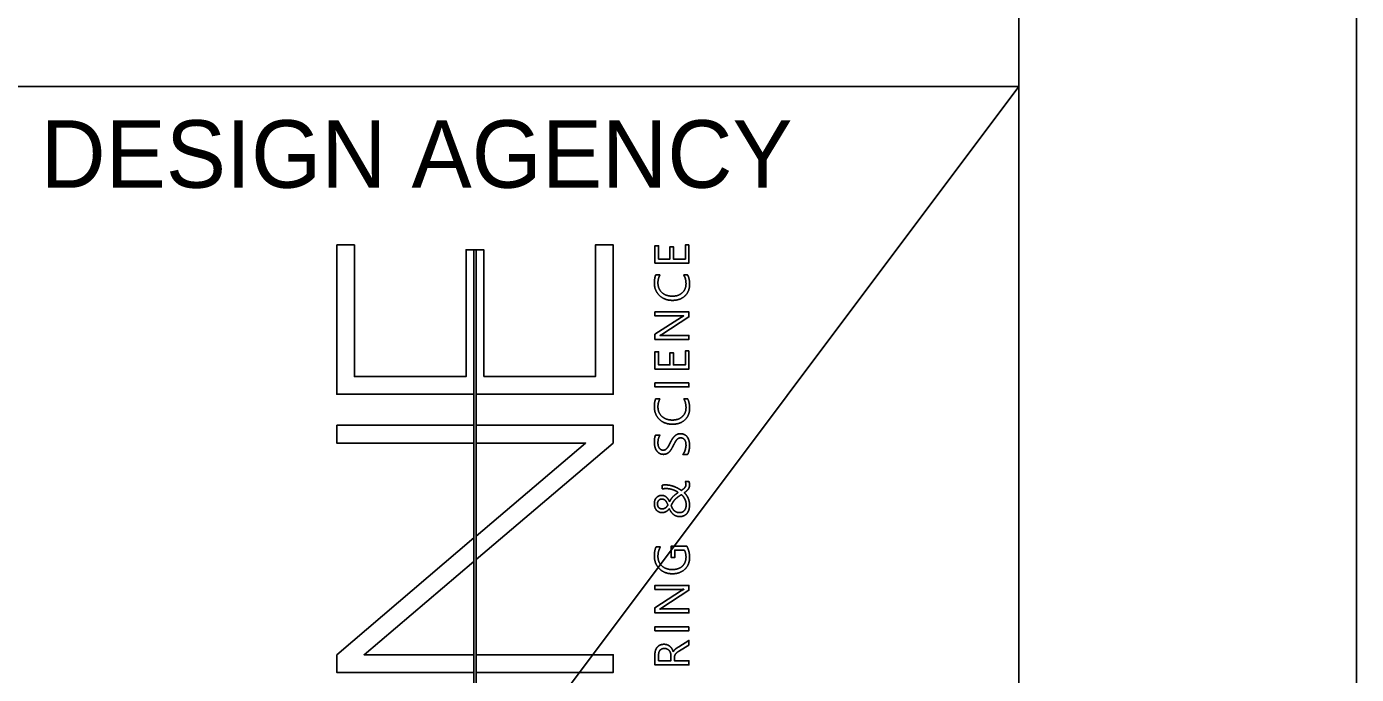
# Model space of a CAD drawing. Extents: x -2 to 1376856, y -4 to 32.
# Drawn here: x 32.029 to 34, y 4.129 to 5.089 of the extents above; entities that cross this region are included whole.
import ezdxf

# ---------------------------------------------------------------- set-up
doc = ezdxf.new("R2010")
doc.units = 0
for name, color, linetype in [('SC_Scratch1', 7, 'Continuous'), ('SH_Border', 7, 'Continuous'), ('SH_Cut_Line', 7, 'Continuous'), ('SH_Data', 7, 'Continuous')]:
    doc.layers.add(name, color=color, linetype=linetype)

msp = doc.modelspace()

# ---------------------------------------------------------------- linework, layer by layer
at = {"layer": 'SC_Scratch1'}
msp.add_line((32, 3), (33.5, 5), dxfattribs=at)
at = {"layer": 'SH_Border'}
msp.add_line((32, 5), (33.5, 5), dxfattribs=at)
msp.add_lwpolyline([(1.5, 21.5), (33.5, 21.5), (33.5, 0.5), (1.5, 0.5)], close=True, dxfattribs=at)
at = {"layer": 'SH_Cut_Line'}
msp.add_lwpolyline([(0, 0), (34, 0), (34, 22), (0, 22)], close=True, dxfattribs=at)
at = {"layer": 'SH_Data'}
for p, q in [((32.489, 4.7652), (32.5153, 4.7652)), ((32.489, 4.5439), (32.489, 4.7652)), ((32.5153, 4.5702), (32.5153, 4.7652)), ((32.6807, 4.5702), (32.6807, 4.7581)), ((32.6807, 4.7581), (32.6923, 4.7581)), ((32.6923, 4.7581), (32.6923, 3.9731)), ((32.6923, 4.7581), (32.6923, 4.5439)), ((32.6923, 4.7581), (32.6954, 4.7581)), ((32.6954, 4.7581), (32.6954, 3.9731)), ((32.6954, 4.7581), (32.6954, 4.5439)), ((32.6954, 4.7581), (32.707, 4.7581)), ((32.707, 4.5702), (32.707, 4.7581)), ((32.8724, 4.7652), (32.8988, 4.7652)), ((32.8724, 4.5702), (32.8724, 4.7652)), ((32.8988, 4.5439), (32.8988, 4.7652)), ((32.9617, 4.7208), (32.968, 4.7208)), ((33.0032, 4.7208), (33.0089, 4.7208)), ((33.0035, 4.6602), (33.0035, 4.6603)), ((32.9676, 4.631), (32.9676, 4.6308)), ((32.5153, 4.5702), (32.6807, 4.5702)), ((32.707, 4.5702), (32.8724, 4.5702)), ((32.489, 4.5439), (32.6923, 4.5439)), ((32.6954, 4.5439), (32.8988, 4.5439)), ((32.9617, 4.5373), (32.968, 4.5373)), ((33.0032, 4.5373), (33.0089, 4.5373)), ((32.489, 4.4717), (32.489, 4.4981)), ((32.489, 4.4981), (32.6923, 4.4981)), ((32.6923, 4.4981), (32.6923, 4.4717)), ((32.6954, 4.4981), (32.6954, 4.4717)), ((32.6954, 4.4981), (32.8988, 4.4981)), ((32.8988, 4.4717), (32.8988, 4.4981)), ((32.9615, 4.4834), (32.9681, 4.4834)), ((32.489, 4.4717), (32.6923, 4.4717)), ((32.6954, 4.3337), (32.8577, 4.4717)), ((32.8988, 4.4717), (32.6954, 4.2989)), ((32.6954, 4.4717), (32.8577, 4.4717)), ((33.009, 4.4549), (33.002, 4.4549)), ((33.0109, 4.4148), (33.0055, 4.4148)), ((32.9715, 4.4092), (32.9715, 4.4036)), ((33.0118, 4.4094), (33.0118, 4.4094)), ((32.9709, 4.3886), (32.9709, 4.3886)), ((33.0068, 4.3798), (33.0068, 4.3798)), ((32.489, 4.158), (32.6923, 4.331)), ((32.6923, 4.331), (32.6923, 4.2962)), ((32.6954, 4.3337), (32.6954, 4.2989)), ((32.9623, 4.318), (32.9689, 4.318)), ((32.6923, 4.2962), (32.5296, 4.158)), ((33.0035, 4.255), (33.0035, 4.2551)), ((32.9676, 4.2258), (32.9676, 4.2256)), ((32.489, 4.1316), (32.489, 4.158)), ((32.5296, 4.158), (32.6923, 4.158)), ((32.6923, 4.158), (32.6923, 4.1316)), ((32.6954, 4.158), (32.6954, 4.1316)), ((32.6954, 4.158), (32.8988, 4.158)), ((32.8988, 4.1316), (32.8988, 4.158)), ((32.9877, 4.1622), (32.9876, 4.1622)), ((32.489, 4.1316), (32.6923, 4.1316)), ((32.6954, 4.1316), (32.8988, 4.1316))]:
    msp.add_line(p, q, dxfattribs=at)
for points in [[(32.489, 4.7652), (32.489, 4.5439), (32.6923, 4.5439), (32.6923, 4.7581), (32.6807, 4.7581), (32.6807, 4.5702), (32.5153, 4.5702), (32.5153, 4.7652)], [(32.707, 4.5702), (32.707, 4.7581), (32.6954, 4.7581), (32.6954, 4.5439), (32.8988, 4.5439), (32.8988, 4.7652), (32.8724, 4.7652), (32.8724, 4.5702)], [(33.011, 4.7652), (33.011, 4.7384), (32.9605, 4.7384), (32.9605, 4.7641), (32.9659, 4.7641), (32.9659, 4.7443), (32.9827, 4.7443), (32.9827, 4.7626), (32.988, 4.7626), (32.988, 4.7443), (33.0057, 4.7443), (33.0057, 4.7652)], [(33.011, 4.6081), (33.011, 4.5813), (32.9605, 4.5813), (32.9605, 4.607), (32.9659, 4.607), (32.9659, 4.5873), (32.9827, 4.5873), (32.9827, 4.6055), (32.988, 4.6055), (32.988, 4.5873), (33.0057, 4.5873), (33.0057, 4.6081)], [(33.011, 4.5607), (33.011, 4.5548), (32.9605, 4.5548), (32.9605, 4.5607)], [(32.489, 4.4981), (32.489, 4.4717), (32.6923, 4.4717), (32.6923, 4.4981)], [(32.6954, 4.4981), (32.6954, 4.4717), (32.8577, 4.4717), (32.6954, 4.3337), (32.6954, 4.2989), (32.8988, 4.4717), (32.8988, 4.4981)], [(32.489, 4.158), (32.489, 4.1316), (32.6923, 4.1316), (32.6923, 4.158), (32.5296, 4.158), (32.6923, 4.2962), (32.6923, 4.331)], [(33.011, 4.1993), (33.011, 4.1934), (32.9605, 4.1934), (32.9605, 4.1993)], [(32.6954, 4.158), (32.6954, 4.1316), (32.8988, 4.1316), (32.8988, 4.158)]]:
    msp.add_lwpolyline(points, close=True, dxfattribs=at)
for points in [[(32.8317, 3.9686), (32.6986, 3.9356), (32.6986, 3.9731), (32.6954, 3.9731), (32.6954, 4.7581), (32.6923, 4.7581), (32.6923, 3.9731), (32.6891, 3.9731), (32.6891, 3.9333), (32.6149, 3.9149)], [(32.9961, 4.66), (32.9605, 4.66), (32.9605, 4.6659), (33.011, 4.6659), (33.011, 4.6586), (32.9708, 4.6326)], [(32.9745, 4.6311), (33.011, 4.6311), (33.011, 4.6252), (32.9605, 4.6252), (32.9605, 4.6328), (33.0001, 4.6581)], [(33.0042, 4.3131), (32.99, 4.3131), (32.99, 4.302), (32.9847, 4.302), (32.9847, 4.319), (33.0076, 4.319)], [(32.9961, 4.2547), (32.9605, 4.2547), (32.9605, 4.2607), (33.011, 4.2607), (33.011, 4.2534), (32.9708, 4.2274)], [(32.9745, 4.2258), (33.011, 4.2258), (33.011, 4.2199), (32.9605, 4.2199), (32.9605, 4.2276), (33.0001, 4.2529)], [(32.9969, 4.1637), (33.011, 4.1721), (33.011, 4.1792), (32.9958, 4.1697)], [(32.9605, 4.158), (32.9605, 4.1429), (33.011, 4.1429), (33.011, 4.1489), (32.9895, 4.1489), (32.9895, 4.1537)], [(32.9842, 4.1569), (32.9842, 4.1489), (32.9659, 4.1489), (32.9659, 4.157)]]:
    msp.add_lwpolyline(points, dxfattribs=at)
for points in [[(32.9597, 4.7089), (32.9597, 4.7161), (32.9617, 4.7208)], [(32.968, 4.7208), (32.965, 4.7154), (32.965, 4.7089)], [(33.0066, 4.7077), (33.0066, 4.7153), (33.0032, 4.7208)], [(33.0089, 4.7208), (33.0119, 4.7152), (33.0119, 4.7069)], [(32.9671, 4.6904), (32.9597, 4.6977), (32.9597, 4.7089)], [(32.965, 4.7089), (32.965, 4.7002), (32.9708, 4.6947)], [(32.9867, 4.6831), (32.9746, 4.6831), (32.9671, 4.6904)], [(32.9708, 4.6947), (32.9766, 4.6893), (32.9864, 4.6893)], [(32.9864, 4.6893), (32.9956, 4.6893), (33.0011, 4.6944)], [(33.0011, 4.6944), (33.0066, 4.6994), (33.0066, 4.7077)], [(33.0119, 4.7069), (33.0119, 4.6961), (33.0049, 4.6896)], [(33.0049, 4.6896), (32.998, 4.6831), (32.9867, 4.6831)], [(33.0035, 4.6603), (33.0013, 4.66), (32.9961, 4.66)], [(33.0001, 4.6581), (33.0026, 4.6597), (33.0035, 4.6602)], [(32.9708, 4.6326), (32.9692, 4.6316), (32.9676, 4.631)], [(32.9676, 4.6308), (32.9692, 4.6311), (32.9745, 4.6311)], [(32.9597, 4.5253), (32.9597, 4.5325), (32.9617, 4.5373)], [(32.968, 4.5373), (32.965, 4.5318), (32.965, 4.5253)], [(33.0066, 4.5241), (33.0066, 4.5317), (33.0032, 4.5373)], [(33.0089, 4.5373), (33.0119, 4.5316), (33.0119, 4.5233)], [(32.9671, 4.5068), (32.9597, 4.5141), (32.9597, 4.5253)], [(32.965, 4.5253), (32.965, 4.5166), (32.9708, 4.5112)], [(33.0011, 4.5108), (33.0066, 4.5159), (33.0066, 4.5241)], [(33.0119, 4.5233), (33.0119, 4.5125), (33.0049, 4.506)], [(32.9867, 4.4995), (32.9746, 4.4995), (32.9671, 4.5068)], [(32.9708, 4.5112), (32.9766, 4.5057), (32.9864, 4.5057)], [(32.9864, 4.5057), (32.9956, 4.5057), (33.0011, 4.5108)], [(33.0049, 4.506), (32.998, 4.4995), (32.9867, 4.4995)], [(32.9597, 4.4725), (32.9597, 4.4799), (32.9615, 4.4834)], [(32.9681, 4.4834), (32.965, 4.4789), (32.965, 4.4719)], [(32.9832, 4.4721), (32.9845, 4.4748), (32.986, 4.4772)], [(32.986, 4.4772), (32.9875, 4.4797), (32.9893, 4.4815)], [(32.9893, 4.4815), (32.9911, 4.4833), (32.9933, 4.4844)], [(32.9924, 4.4759), (32.9911, 4.4743), (32.99, 4.4721)], [(32.9951, 4.4784), (32.9936, 4.4775), (32.9924, 4.4759)], [(32.9933, 4.4844), (32.9955, 4.4855), (32.9983, 4.4855)], [(32.9987, 4.4793), (32.9967, 4.4793), (32.9951, 4.4784)], [(32.9983, 4.4855), (33.002, 4.4855), (33.0046, 4.484)], [(33.0045, 4.4766), (33.0025, 4.4793), (32.9987, 4.4793)], [(33.0066, 4.4684), (33.0066, 4.4739), (33.0045, 4.4766)], [(33.0046, 4.484), (33.0072, 4.4826), (33.0088, 4.4801)], [(33.0088, 4.4801), (33.0104, 4.4776), (33.0112, 4.4743)], [(33.0112, 4.4743), (33.0119, 4.4711), (33.0119, 4.4675)], [(32.9605, 4.466), (32.9597, 4.4692), (32.9597, 4.4725)], [(32.9629, 4.4604), (32.9613, 4.4629), (32.9605, 4.466)], [(32.9671, 4.4564), (32.9646, 4.458), (32.9629, 4.4604)], [(32.965, 4.4719), (32.965, 4.4699), (32.9654, 4.468)], [(32.9654, 4.468), (32.9658, 4.4661), (32.9667, 4.4645)], [(32.9667, 4.4645), (32.9677, 4.463), (32.9691, 4.4621)], [(32.9732, 4.4549), (32.9697, 4.4549), (32.9671, 4.4564)], [(32.9691, 4.4621), (32.9705, 4.4611), (32.9726, 4.4611)], [(32.9726, 4.4611), (32.9746, 4.4611), (32.976, 4.4618)], [(32.9781, 4.4559), (32.976, 4.4549), (32.9732, 4.4549)], [(32.976, 4.4618), (32.9774, 4.4626), (32.9785, 4.464)], [(32.9818, 4.4586), (32.9802, 4.4569), (32.9781, 4.4559)], [(32.9785, 4.464), (32.9797, 4.4654), (32.9808, 4.4674)], [(32.9808, 4.4674), (32.9819, 4.4694), (32.9832, 4.4721)], [(32.9849, 4.4625), (32.9835, 4.4602), (32.9818, 4.4586)], [(32.9876, 4.4675), (32.9862, 4.4648), (32.9849, 4.4625)], [(32.99, 4.4721), (32.9888, 4.47), (32.9876, 4.4675)], [(33.002, 4.4549), (33.0031, 4.4561), (33.0039, 4.4577)], [(33.0039, 4.4577), (33.0048, 4.4594), (33.0053, 4.4612)], [(33.0053, 4.4612), (33.0059, 4.4631), (33.0062, 4.465)], [(33.0062, 4.465), (33.0066, 4.4668), (33.0066, 4.4684)], [(33.0102, 4.4575), (33.0097, 4.4558), (33.009, 4.4549)], [(33.0111, 4.461), (33.0108, 4.4591), (33.0102, 4.4575)], [(33.0117, 4.4645), (33.0115, 4.4628), (33.0111, 4.461)], [(33.0119, 4.4675), (33.0119, 4.4663), (33.0117, 4.4645)], [(33.0055, 4.4148), (33.0059, 4.4136), (33.0062, 4.4125)], [(33.0116, 4.4121), (33.0114, 4.4135), (33.0109, 4.4148)], [(32.9737, 4.4095), (32.9727, 4.4095), (32.9715, 4.4092)], [(32.9715, 4.4036), (32.9727, 4.4039), (32.9739, 4.404)], [(32.9762, 4.4096), (32.9748, 4.4096), (32.9737, 4.4095)], [(32.9739, 4.404), (32.9751, 4.4042), (32.9764, 4.4042)], [(32.9827, 4.409), (32.9794, 4.4096), (32.9762, 4.4096)], [(32.9764, 4.4042), (32.9816, 4.4042), (32.9864, 4.4027)], [(32.989, 4.4072), (32.9859, 4.4083), (32.9827, 4.409)], [(32.9864, 4.4027), (32.9912, 4.4013), (32.9952, 4.3984)], [(32.9912, 4.3956), (32.9893, 4.3941), (32.9876, 4.3925)], [(32.9948, 4.4045), (32.992, 4.406), (32.989, 4.4072)], [(32.9952, 4.3984), (32.9931, 4.397), (32.9912, 4.3956)], [(32.994, 4.3912), (32.9964, 4.393), (32.9998, 4.3952)], [(32.9998, 4.4014), (32.9975, 4.403), (32.9948, 4.4045)], [(33.0027, 4.4036), (33.0015, 4.4026), (32.9998, 4.4014)], [(32.9998, 4.3952), (33.0012, 4.3939), (33.0025, 4.3924)], [(33.0048, 4.4057), (33.004, 4.4047), (33.0027, 4.4036)], [(33.004, 4.3979), (33.0059, 4.3993), (33.0073, 4.4005)], [(33.007, 4.3947), (33.0055, 4.3965), (33.004, 4.3979)], [(33.0061, 4.4079), (33.0057, 4.4067), (33.0048, 4.4057)], [(33.0065, 4.4104), (33.0065, 4.409), (33.0061, 4.4079)], [(33.0062, 4.4125), (33.0065, 4.4114), (33.0065, 4.4104)], [(33.0095, 4.3906), (33.0084, 4.3928), (33.007, 4.3947)], [(33.0073, 4.4005), (33.0087, 4.4017), (33.0098, 4.403)], [(33.0098, 4.403), (33.0108, 4.4043), (33.0113, 4.4059)], [(33.0113, 4.4059), (33.0118, 4.4074), (33.0118, 4.4094)], [(33.0118, 4.4094), (33.0118, 4.4107), (33.0116, 4.4121)], [(32.9604, 4.3867), (32.9597, 4.3844), (32.9597, 4.3817)], [(32.9597, 4.3817), (32.9597, 4.3789), (32.9604, 4.3765)], [(32.9626, 4.3906), (32.9612, 4.389), (32.9604, 4.3867)], [(32.9604, 4.3765), (32.9612, 4.3741), (32.9627, 4.3723)], [(32.966, 4.3931), (32.964, 4.3922), (32.9626, 4.3906)], [(32.9643, 4.3817), (32.9643, 4.3829), (32.9646, 4.3841)], [(32.9661, 4.3761), (32.9643, 4.3782), (32.9643, 4.3817)], [(32.9646, 4.3841), (32.965, 4.3853), (32.9658, 4.3863)], [(32.9658, 4.3863), (32.9666, 4.3873), (32.9679, 4.388)], [(32.9704, 4.3941), (32.9679, 4.3941), (32.966, 4.3931)], [(32.9712, 4.374), (32.968, 4.3741), (32.9661, 4.3761)], [(32.9679, 4.388), (32.9691, 4.3886), (32.9709, 4.3886)], [(32.9774, 4.3916), (32.9746, 4.3941), (32.9704, 4.3941)], [(32.9709, 4.3886), (32.974, 4.3886), (32.9761, 4.3864)], [(32.9763, 4.3757), (32.9752, 4.3749), (32.9739, 4.3745)], [(32.9761, 4.3864), (32.9781, 4.3843), (32.9797, 4.3798)], [(32.9782, 4.3776), (32.9774, 4.3765), (32.9763, 4.3757)], [(32.9822, 4.3844), (32.9802, 4.3892), (32.9774, 4.3916)], [(32.9797, 4.3798), (32.9791, 4.3786), (32.9782, 4.3776)], [(32.9845, 4.3888), (32.9831, 4.3868), (32.9822, 4.3844)], [(32.9876, 4.3925), (32.9859, 4.3908), (32.9845, 4.3888)], [(32.9847, 4.3788), (32.9857, 4.3815), (32.987, 4.3836)], [(32.9866, 4.3747), (32.9856, 4.3765), (32.9847, 4.3788)], [(32.9892, 4.3715), (32.9877, 4.3728), (32.9866, 4.3747)], [(32.987, 4.3836), (32.9882, 4.3857), (32.9899, 4.3876)], [(32.9899, 4.3876), (32.9917, 4.3894), (32.994, 4.3912)], [(33.0025, 4.3924), (33.0037, 4.3908), (33.0047, 4.3889)], [(33.0062, 4.3754), (33.0056, 4.3734), (33.0044, 4.3718)], [(33.0047, 4.3889), (33.0057, 4.387), (33.0063, 4.3848)], [(33.0068, 4.3798), (33.0068, 4.3775), (33.0062, 4.3754)], [(33.0063, 4.3848), (33.0068, 4.3825), (33.0068, 4.3798)], [(33.0112, 4.3856), (33.0105, 4.3883), (33.0095, 4.3906)], [(33.0109, 4.3728), (33.0118, 4.376), (33.0118, 4.3798)], [(33.0118, 4.3798), (33.0118, 4.383), (33.0112, 4.3856)], [(32.9627, 4.3723), (32.9641, 4.3706), (32.9663, 4.3696)], [(32.9663, 4.3696), (32.9684, 4.3685), (32.9712, 4.3685)], [(32.9739, 4.3745), (32.9727, 4.374), (32.9712, 4.374)], [(32.9712, 4.3685), (32.9731, 4.3685), (32.9747, 4.3691)], [(32.9747, 4.3691), (32.9763, 4.3696), (32.9776, 4.3704)], [(32.9776, 4.3704), (32.979, 4.3712), (32.98, 4.3723)], [(32.98, 4.3723), (32.981, 4.3733), (32.9818, 4.3744)], [(32.9818, 4.3744), (32.9843, 4.3688), (32.9881, 4.3657)], [(32.9881, 4.3657), (32.9919, 4.3627), (32.9973, 4.3627)], [(32.9926, 4.3693), (32.9906, 4.3701), (32.9892, 4.3715)], [(32.9971, 4.3685), (32.9945, 4.3685), (32.9926, 4.3693)], [(33.0013, 4.3694), (32.9995, 4.3685), (32.9971, 4.3685)], [(32.9973, 4.3627), (33.0008, 4.3627), (33.0035, 4.3639)], [(33.0044, 4.3718), (33.0032, 4.3703), (33.0013, 4.3694)], [(33.0035, 4.3639), (33.0062, 4.3652), (33.0081, 4.3674)], [(33.0081, 4.3674), (33.0099, 4.3697), (33.0109, 4.3728)], [(32.9597, 4.3041), (32.9597, 4.3124), (32.9623, 4.318)], [(32.9689, 4.318), (32.965, 4.3118), (32.965, 4.3035)], [(33.0076, 4.319), (33.0119, 4.3114), (33.0119, 4.3021)], [(32.9672, 4.2853), (32.9597, 4.2927), (32.9597, 4.3041)], [(32.965, 4.3035), (32.965, 4.295), (32.9709, 4.2895)], [(33.0011, 4.2891), (33.0066, 4.2942), (33.0066, 4.3028)], [(33.0066, 4.3028), (33.0066, 4.3087), (33.0042, 4.3131)], [(33.0119, 4.3021), (33.0119, 4.2913), (33.0049, 4.2846)], [(32.9864, 4.2779), (32.9747, 4.2779), (32.9672, 4.2853)], [(32.9709, 4.2895), (32.9767, 4.2841), (32.986, 4.2841)], [(32.986, 4.2841), (32.9956, 4.2841), (33.0011, 4.2891)], [(33.0049, 4.2846), (32.9979, 4.2779), (32.9864, 4.2779)], [(33.0035, 4.2551), (33.0013, 4.2547), (32.9961, 4.2547)], [(33.0001, 4.2529), (33.0026, 4.2545), (33.0035, 4.255)], [(32.9708, 4.2274), (32.9692, 4.2264), (32.9676, 4.2258)], [(32.9676, 4.2256), (32.9692, 4.2258), (32.9745, 4.2258)], [(32.9613, 4.1641), (32.9605, 4.1613), (32.9605, 4.158)], [(32.9638, 4.169), (32.9622, 4.1669), (32.9613, 4.1641)], [(32.9681, 4.1722), (32.9655, 4.1711), (32.9638, 4.169)], [(32.9659, 4.157), (32.9659, 4.1619), (32.9681, 4.1646)], [(32.974, 4.1734), (32.9706, 4.1734), (32.9681, 4.1722)], [(32.9681, 4.1646), (32.9704, 4.1672), (32.9745, 4.1672)], [(32.9788, 4.1726), (32.9766, 4.1734), (32.974, 4.1734)], [(32.9745, 4.1672), (32.9767, 4.1672), (32.9785, 4.1664)], [(32.9785, 4.1664), (32.9803, 4.1656), (32.9816, 4.1643)], [(32.9827, 4.1703), (32.981, 4.1718), (32.9788, 4.1726)], [(32.9816, 4.1643), (32.9828, 4.1629), (32.9835, 4.161)], [(32.9857, 4.1668), (32.9845, 4.1689), (32.9827, 4.1703)], [(32.9835, 4.161), (32.9842, 4.1591), (32.9842, 4.1569)], [(32.9876, 4.1622), (32.9869, 4.1648), (32.9857, 4.1668)], [(32.989, 4.1644), (32.9883, 4.1635), (32.9877, 4.1622)], [(32.9907, 4.1662), (32.9897, 4.1653), (32.989, 4.1644)], [(32.9899, 4.1567), (32.9904, 4.158), (32.9912, 4.1592)], [(32.9929, 4.1678), (32.9917, 4.167), (32.9907, 4.1662)], [(32.9912, 4.1592), (32.9921, 4.1603), (32.9935, 4.1614)], [(32.9958, 4.1697), (32.9942, 4.1687), (32.9929, 4.1678)], [(32.9935, 4.1614), (32.9949, 4.1625), (32.9969, 4.1637)], [(32.9895, 4.1537), (32.9895, 4.1554), (32.9899, 4.1567)]]:
    msp.add_open_spline(points, degree=2, dxfattribs=at)

# ---------------------------------------------------------------- texts
msp.add_text('DESIGN AGENCY', height=0.1, dxfattribs=at).set_placement((32.05, 4.85))

doc.saveas('drawing.dxf')
